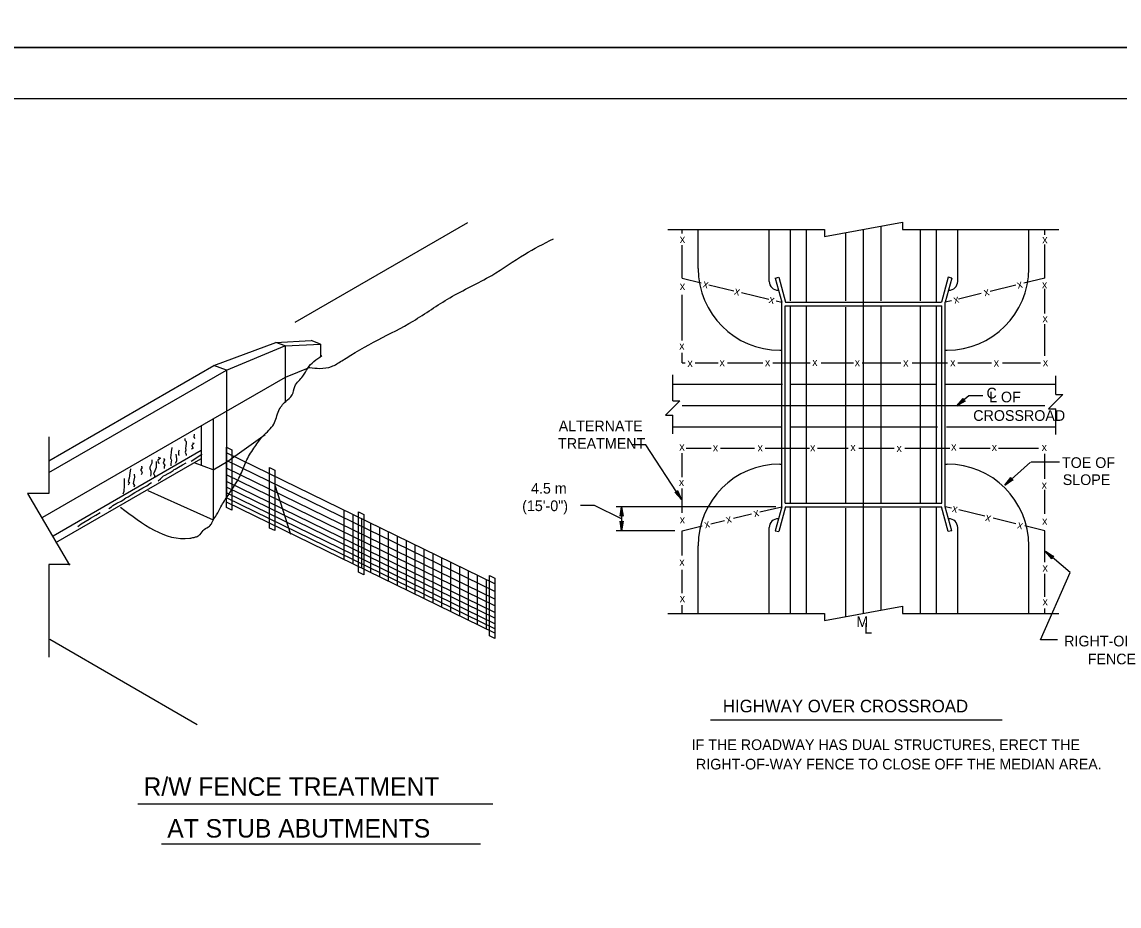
# Model space of a CAD drawing. Extents: x 13 to 918, y -903 to 879.
# Drawn here: x 370 to 691.5, y -560.6 to -301.6 of the extents above; entities that cross this region are included whole.
import ezdxf

# ---------------------------------------------------------------- set-up
doc = ezdxf.new("R2010")
doc.units = 0
for name, color, linetype in [('1', 7, 'Continuous'), ('3', 7, 'Continuous'), ('PLT-BNDY', 7, 'Continuous')]:
    doc.layers.add(name, color=color, linetype=linetype)

msp = doc.modelspace()

# ---------------------------------------------------------------- linework, layer by layer
at = {"layer": '1'}
for p, q in [((444.36025, -395.4985), (454.8145, -394.9505)), ((447.1185, -396.45475), (447.1185, -413.01725)), ((447.13725, -396.486), (457.53525, -395.94025)), ((457.53525, -395.94025), (457.53525, -399.6465)), ((429.931, -403.5735), (429.931, -440.96725)), ((426.0435, -417.8485), (426.0435, -432.71525)), ((422.56225, -419.78175), (422.56225, -431.4255)), ((377.89575, -423.088), (377.89575, -439.75475)), ((429.931, -443.861), (429.931, -426.15275)), ((429.931, -426.15275), (431.4935, -426.91525)), ((431.4935, -426.91525), (431.4935, -444.6235)), ((426.0435, -432.71525), (426.0435, -447.58175)), ((442.58525, -449.8485), (442.58525, -432.14025)), ((442.58525, -432.14025), (444.14775, -432.90275)), ((444.14775, -432.90275), (444.14775, -450.611)), ((377.89575, -439.75475), (371.64575, -439.75475)), ((371.64575, -439.75475), (383.9165, -460.69225)), ((444.16025, -437.26525), (448.66225, -451.69225)), ((431.4935, -444.6235), (429.931, -443.861)), ((464.3435, -444.5735), (464.3435, -459.05475)), ((466.94975, -445.84425), (466.94975, -460.3255)), ((468.627, -462.81925), (468.627, -445.111)), ((468.627, -445.111), (470.1895, -445.8735)), ((470.1895, -445.8735), (470.1895, -463.58175)), ((444.14775, -450.611), (442.58525, -449.8485)), ((469.554, -447.11525), (469.554, -461.5965)), ((472.15825, -448.386), (472.15825, -462.86725)), ((474.7645, -449.65675), (474.7645, -464.138)), ((477.3685, -450.92775), (477.3685, -465.409)), ((479.97475, -452.1985), (479.97475, -466.67975)), ((482.579, -453.46725), (482.579, -467.9485)), ((485.18325, -454.738), (485.18325, -469.21925)), ((487.7895, -456.009), (487.7895, -470.49025)), ((490.3935, -457.27975), (490.3935, -471.761)), ((492.99975, -458.5505), (492.99975, -473.03175)), ((384.14575, -460.588), (377.89575, -460.588)), ((377.89575, -460.588), (377.89575, -487.6715)), ((470.1895, -463.58175), (468.627, -462.81925)), ((495.604, -459.8215), (495.604, -474.30275)), ((498.20825, -461.09025), (498.20825, -475.5715)), ((500.8145, -462.363), (500.8145, -476.84425)), ((503.4185, -463.63175), (503.4185, -478.113)), ((506.02475, -464.90275), (506.02475, -479.3505)), ((507.054, -481.4465), (507.054, -463.738)), ((507.054, -463.738), (508.6165, -464.5005)), ((508.6165, -464.5005), (508.6165, -482.209)), ((508.629, -466.1735), (508.629, -479.3505)), ((605.1475, -476.938), (628.064, -472.7715)), ((605.1475, -474.85475), (605.1475, -476.938)), ((628.064, -472.7715), (628.064, -474.85475)), ((508.6165, -482.209), (507.054, -481.4465))]:
    msp.add_line(p, q, dxfattribs=at)
for points in [[(837.2505, -888.06975), (837.2505, -324.06975), (51.2505, -324.06975), (51.2505, -888.06975), (837.2505, -888.06975), (837.2505, -861.71075), (637.2505, -861.71075), (637.2505, -797.03325), (837.2505, -797.03325), (837.2505, -768.06975), (637.2505, -768.06975), (637.2505, -888.06975), (716.052, -888.06975), (716.052, -861.71075), (716.052, -888.06975), (793.052, -888.06975), (793.052, -861.71075), (793.052, -874.02725), (837.2505, -874.02725)], [(605.1475, -362.35475), (605.1475, -364.438), (628.064, -360.2715), (628.064, -362.35475)], [(646.21825, -412.62975), (646.0225, -412.54225), (643.9495, -414.036), (646.21825, -412.62975), (646.3975, -412.636), (643.9495, -414.036), (645.8515, -412.336), (645.80575, -412.12975), (643.9495, -414.036), (645.837, -411.94225), (645.80575, -412.12975)], [(417.779, -423.5965), (417.702, -424.15475), (418.181, -424.538), (418.106, -425.0965), (418.029, -425.73175), (417.952, -426.5215), (418.029, -427.07775), (417.854, -427.636), (418.181, -428.2715), (418.106, -428.57975)], [(420.47075, -422.32775), (420.39575, -423.19225), (420.702, -423.5965)], [(413.91225, -426.29025), (413.75825, -427.559), (413.75825, -427.86725), (413.604, -428.4255), (413.50825, -429.36725), (413.83525, -430.00275), (413.75825, -430.388), (413.604, -431.0985), (413.681, -431.65675)], [(416.12275, -427.0005), (415.8935, -427.386), (415.8935, -428.4255), (416.04775, -428.50275)], [(419.9895, -424.86525), (420.47075, -425.01925), (419.76025, -425.65475), (419.83725, -425.809), (420.1645, -426.44425), (419.68325, -426.7505)], [(408.0645, -429.8485), (408.0645, -430.86725), (407.506, -431.984), (407.506, -432.36925), (407.73725, -433.234), (407.73725, -434.11925), (407.66025, -434.65675)], [(409.3145, -430.386), (409.3145, -432.138), (408.91025, -433.07975), (408.602, -434.0235), (408.756, -434.1965), (408.91025, -434.811)], [(409.9685, -429.059), (410.58325, -429.36725), (409.87275, -429.9255), (409.9685, -430.713), (410.19775, -430.86725), (410.12275, -430.94425)], [(409.8915, -436.061), (410.62275, -435.42775), (411.2185, -434.82975), (411.506, -434.6005), (412.006, -434.3505), (412.83525, -433.90675), (413.4685, -433.561), (414.3145, -433.0235), (414.604, -432.734), (414.8935, -432.61925), (415.931, -432.04225), (417.0665, -431.3485), (418.181, -430.75275)], [(411.47075, -429.44425), (411.777, -429.90475), (411.54775, -430.386), (411.3935, -430.86725), (411.854, -431.484), (411.69975, -431.963), (411.69975, -432.44425)], [(415.104, -428.1755), (415.25825, -429.5985), (415.354, -430.311), (414.94975, -430.9465)], [(419.606, -430.234), (422.76025, -428.1755), (422.56225, -428.29425)], [(401.81225, -432.54025), (401.65825, -433.79225), (401.427, -435.21525), (401.177, -436.25275), (401.504, -436.484), (401.09975, -437.2735)], [(404.90825, -431.811), (405.1395, -431.811), (405.1395, -432.29225), (404.73525, -432.8485), (405.06225, -433.15675), (405.2935, -433.71525), (404.98525, -434.2735)], [(395.502, -444.1215), (396.252, -443.67975), (396.579, -443.3715), (396.6935, -443.2755), (397.8685, -442.54425), (399.13725, -441.9485), (399.5415, -441.659), (400.427, -441.0255), (401.15825, -440.67775), (401.98525, -440.14025), (403.12075, -439.4485), (404.004, -438.909), (404.254, -438.71725), (405.4665, -438.11925), (406.602, -437.4465), (407.48725, -436.79225), (407.98725, -436.563)], [(400.004, -435.39025), (399.927, -437.3505), (399.84975, -439.17975), (399.59975, -439.89025)], [(402.927, -434.04225), (403.004, -434.90675), (402.84975, -435.8505), (402.59975, -436.79225), (403.004, -437.42775), (402.84975, -437.909)], [(660.24525, -435.738), (660.04525, -435.661), (658.0495, -437.25475), (660.24525, -435.738), (660.4245, -435.734), (658.0495, -437.25475), (659.86625, -435.463), (659.80775, -435.259), (658.0495, -437.25475), (659.83075, -435.06925), (659.80775, -435.259)], [(562.0765, -439.05275), (561.97025, -439.24025), (563.2515, -441.4485), (562.0765, -439.05275), (562.0975, -438.8755), (563.2515, -441.4485), (561.7475, -439.388), (561.539, -439.413), (563.2515, -441.4485), (561.35375, -439.363), (561.539, -439.413)], [(386.42275, -449.43175), (387.3645, -448.64225), (389.731, -447.21925), (390.13525, -446.988), (391.71225, -446.10275), (392.98325, -445.31525)], [(671.78075, -458.69225), (671.82875, -458.48175), (669.9765, -456.7235), (671.78075, -458.69225), (671.80775, -458.86925), (669.9765, -456.7235), (671.9995, -458.27775), (672.19325, -458.19225), (669.9765, -456.7235), (672.385, -458.19025), (672.19325, -458.19225)]]:
    msp.add_lwpolyline(points, dxfattribs=at)
for points in [[(454.26025, -402.7715), (457.34975, -403.09025), (460.7165, -402.53175), (463.7165, -400.87775), (474.41225, -394.70275), (484.60825, -389.24025), (495.381, -382.39225), (507.67275, -375.83175), (517.31025, -369.6755), (525.731, -365.07775)], [(398.90825, -443.736), (419.206, -452.8215), (420.43525, -452.60475), (421.377, -452.2985), (422.252, -451.71925), (423.43525, -450.24025), (425.01225, -449.27775), (425.64775, -448.336), (426.0435, -447.58175), (427.07075, -445.96925), (428.3415, -443.60275), (430.39975, -440.2755), (431.977, -437.909), (434.3435, -433.638), (435.92075, -429.8485), (438.28725, -426.04025), (440.67275, -422.886), (443.827, -419.40275), (445.24975, -415.459), (447.30825, -412.76725), (449.1935, -410.863), (450.002, -408.34225), (452.3685, -405.34025), (453.7915, -402.9755), (455.52275, -401.0715), (457.8895, -399.34025)]]:
    msp.add_spline(points, degree=3, dxfattribs=at)
at = {"layer": '3'}
for p, q in [((450.0685, -389.54225), (500.656, -360.338)), ((559.314, -362.35475), (605.1475, -362.35475)), ((563.48075, -363.57975), (563.48075, -362.35475)), ((568.16825, -373.813), (568.16825, -362.35475)), ((589.0015, -377.584), (589.0015, -362.35475)), ((595.2515, -383.29025), (595.2515, -362.35475)), ((599.939, -383.4505), (599.939, -362.35475)), ((616.60575, -474.85475), (616.60575, -362.35475)), ((621.814, -383.29025), (621.814, -361.61725)), ((628.064, -362.35475), (673.8975, -362.35475)), ((633.2725, -383.29025), (633.2725, -362.35475)), ((637.96, -383.71925), (637.96, -362.35475)), ((644.21, -377.584), (644.21, -362.35475)), ((665.04325, -373.813), (665.04325, -362.35475)), ((669.73075, -363.963), (669.73075, -362.35475)), ((611.3975, -383.29025), (611.3975, -363.309)), ((563.48075, -376.67775), (563.48075, -366.94425)), ((669.73075, -376.67775), (669.73075, -366.811)), ((563.48075, -376.67775), (569.04525, -378.01925)), ((571.312, -378.56525), (578.61825, -380.3255)), ((590.76, -376.66725), (591.76625, -376.3965)), ((590.76, -376.66725), (592.6475, -383.709)), ((591.76625, -376.3965), (593.7265, -383.709)), ((641.44525, -376.3965), (639.485, -383.709)), ((642.4515, -376.66725), (640.564, -383.709)), ((642.4515, -376.66725), (641.44525, -376.3965)), ((661.23075, -378.7255), (653.71825, -380.538)), ((669.73075, -376.67775), (663.61, -378.15275)), ((563.48075, -394.8965), (563.48075, -381.50675)), ((580.8265, -380.859), (588.90775, -382.80675)), ((591.60575, -380.188), (591.70375, -380.188)), ((641.50775, -380.188), (641.60575, -380.188)), ((651.089, -381.1715), (644.489, -382.763)), ((669.73075, -386.9715), (669.73075, -379.81525)), ((591.04525, -383.3235), (592.6475, -383.709)), ((592.6475, -443.60475), (592.6475, -383.709)), ((593.689, -384.7505), (639.5225, -384.7505)), ((593.689, -442.563), (593.689, -384.7505)), ((593.7265, -383.709), (639.485, -383.709)), ((595.2515, -442.636), (595.2515, -384.69225)), ((599.939, -442.39225), (599.939, -384.89225)), ((611.3975, -442.39225), (611.3975, -385.17775)), ((621.814, -442.636), (621.814, -384.934)), ((633.2725, -442.636), (633.2725, -384.69225)), ((637.96, -442.636), (637.96, -384.69225)), ((639.5225, -442.563), (639.5225, -384.7505)), ((642.38075, -383.2715), (640.564, -383.709)), ((640.564, -443.60475), (640.564, -383.709)), ((669.73075, -399.436), (669.73075, -390.086)), ((457.53525, -395.94025), (454.8145, -394.9505)), ((426.24775, -402.234), (444.42275, -395.4755)), ((429.931, -403.5735), (447.0645, -396.47775)), ((447.1185, -396.45475), (444.42275, -395.4755)), ((563.48075, -401.41725), (563.48075, -398.53175)), ((592.1265, -397.7715), (592.6475, -397.7715)), ((640.564, -397.7715), (641.085, -397.7715)), ((563.48075, -401.41725), (564.40575, -401.41725)), ((567.2725, -401.41725), (574.0245, -401.41725)), ((576.75575, -401.41725), (587.162, -401.41725)), ((590.01, -401.41725), (600.937, -401.41725)), ((604.187, -401.41725), (613.67025, -401.41725)), ((616.26825, -401.41725), (627.57875, -401.41725)), ((630.83075, -401.41725), (641.21825, -401.41725)), ((644.21825, -401.41725), (654.087, -401.41725)), ((657.339, -401.41725), (668.514, -401.41725)), ((377.89575, -430.1465), (426.24775, -402.234)), ((377.9435, -433.586), (429.931, -403.5735)), ((429.931, -403.5735), (426.24775, -402.234)), ((447.23325, -405.61525), (454.46025, -402.69025)), ((560.7015, -412.5715), (560.7015, -404.9755)), ((426.0435, -417.8485), (447.23325, -405.61525)), ((560.7015, -407.66725), (592.85375, -407.66725)), ((595.43075, -407.66725), (637.82875, -407.66725)), ((640.4265, -407.66725), (672.9475, -407.66725)), ((672.9475, -410.7215), (672.9475, -405.284)), ((647.50775, -411.161), (643.9495, -414.036)), ((651.61, -411.161), (647.50775, -411.161)), ((563.48075, -413.91725), (669.73075, -413.91725)), ((376.177, -446.636), (426.0435, -417.8485)), ((560.7015, -422.26925), (560.7015, -416.738)), ((672.9475, -422.4235), (672.9475, -414.888)), ((560.7015, -420.16725), (592.61, -420.16725)), ((595.20775, -420.16725), (638.29525, -420.16725)), ((640.89325, -420.16725), (672.9475, -420.16725)), ((430.37275, -430.26525), (441.27275, -422.4985)), ((379.2145, -452.0985), (422.5415, -427.084)), ((552.787, -425.511), (548.7325, -425.511)), ((563.2515, -441.4485), (552.787, -425.511)), ((564.6745, -426.41725), (571.94525, -426.41725)), ((574.67875, -426.41725), (584.68075, -426.41725)), ((587.7975, -426.41725), (600.8015, -426.41725)), ((603.1475, -426.41725), (612.112, -426.41725)), ((615.22875, -426.41725), (625.61625, -426.41725)), ((628.7515, -426.41725), (641.8725, -426.41725)), ((644.739, -426.41725), (653.7015, -426.41725)), ((656.164, -426.41725), (667.86, -426.41725)), ((379.9685, -454.06925), (422.42475, -429.559)), ((426.0435, -432.76525), (430.37275, -430.26525)), ((508.629, -466.1735), (429.931, -427.79025)), ((508.629, -468.488), (429.931, -430.10475)), ((563.48075, -434.92775), (563.48075, -427.90675)), ((665.5725, -430.53175), (658.0495, -437.25475)), ((674.07875, -430.53175), (665.78275, -430.53175)), ((669.73075, -435.4465), (669.73075, -428.15675)), ((426.0435, -432.76525), (420.73525, -430.834)), ((508.629, -470.661), (429.931, -432.27775)), ((592.1265, -431.10475), (592.6475, -431.10475)), ((640.564, -431.10475), (641.085, -431.10475)), ((508.629, -472.686), (429.931, -434.30275)), ((508.629, -474.56925), (429.931, -436.186)), ((426.181, -447.5965), (406.98725, -439.00475)), ((508.629, -476.309), (429.931, -437.9255)), ((508.629, -477.9005), (429.931, -439.51725)), ((563.48075, -445.4505), (563.48075, -438.29425)), ((669.73075, -445.71925), (669.73075, -438.6985)), ((508.629, -479.3505), (429.931, -440.96725)), ((508.629, -480.65475), (429.931, -442.2715)), ((537.788, -443.27475), (533.7335, -443.27475)), ((545.7475, -447.11925), (537.788, -443.27475)), ((590.96625, -443.60475), (544.1015, -443.60475)), ((545.7475, -443.60475), (545.7475, -450.636)), ((586.25775, -445.14425), (592.6475, -443.60475)), ((592.6475, -443.60475), (590.76, -450.6465)), ((593.7265, -443.60475), (591.76625, -450.91725)), ((593.689, -442.563), (639.5225, -442.563)), ((593.7265, -443.60475), (639.485, -443.60475)), ((641.44525, -450.913), (639.485, -443.60475)), ((642.4515, -450.64225), (640.564, -443.60475)), ((642.387, -444.04425), (640.564, -443.60475)), ((578.5495, -447.00475), (583.78275, -445.74225)), ((595.2515, -474.85475), (595.2515, -443.75675)), ((599.939, -474.85475), (599.939, -443.813)), ((611.3975, -475.72975), (611.3975, -444.05675)), ((621.814, -474.036), (621.814, -444.05675)), ((633.2725, -474.85475), (633.2725, -444.05675)), ((637.96, -474.85475), (637.96, -443.89225)), ((652.164, -446.4005), (644.4995, -444.55275)), ((563.48075, -450.636), (569.38075, -449.213)), ((571.85575, -448.61725), (575.8495, -447.65475)), ((589.0015, -474.85475), (589.0015, -449.72975)), ((591.60575, -447.1255), (591.70375, -447.1255)), ((641.50775, -447.1235), (641.60575, -447.1235)), ((644.21, -474.85475), (644.21, -449.72775)), ((661.239, -448.588), (654.61, -446.99025)), ((669.73075, -450.636), (663.84125, -449.21525)), ((561.29325, -450.636), (544.1015, -450.636)), ((563.48075, -457.934), (563.48075, -450.636)), ((590.76, -450.6465), (591.76625, -450.91725)), ((642.4515, -450.64225), (641.44525, -450.913)), ((669.73075, -459.87775), (669.73075, -450.636)), ((568.16825, -474.85475), (568.16825, -455.063)), ((665.04325, -474.85475), (665.04325, -455.063)), ((677.20775, -462.86725), (669.9765, -456.7235)), ((563.48075, -468.97775), (563.48075, -462.09025)), ((668.514, -482.64425), (677.20775, -462.86725)), ((669.73075, -470.01525), (669.73075, -463.263)), ((563.48075, -474.85475), (563.48075, -472.47775)), ((559.314, -474.85475), (605.1475, -474.85475)), ((628.064, -474.85475), (673.8975, -474.85475)), ((669.73075, -474.85475), (669.73075, -473.4005)), ((421.3645, -507.4715), (378.1935, -482.5465)), ((673.44325, -482.64425), (668.514, -482.64425)), ((571.814, -506.0465), (657.23075, -506.0465)), ((508.0415, -530.7755), (403.9915, -530.7755)), ((504.38325, -542.488), (410.9415, -542.488))]:
    msp.add_line(p, q, dxfattribs=at)
for points in [[(672.9475, -410.7215), (675.03075, -410.7215), (670.864, -414.888), (672.9475, -414.888)], [(560.7015, -412.5715), (562.785, -412.5715), (558.61825, -416.738), (560.7015, -416.738)], [(545.414, -446.25275), (545.60575, -446.15475), (545.7475, -443.60475), (545.414, -446.25275), (545.2995, -446.39025), (545.7475, -443.60475), (545.8725, -446.15275), (546.064, -446.2465), (545.7475, -443.60475), (546.189, -446.39025), (546.064, -446.2465)], [(546.08075, -447.988), (545.889, -448.086), (545.7475, -450.636), (546.08075, -447.988), (546.19525, -447.8505), (545.7475, -450.636), (545.6225, -448.088), (545.43075, -447.99425), (545.7475, -450.636), (545.30575, -447.8505), (545.43075, -447.99425)]]:
    msp.add_lwpolyline(points, dxfattribs=at)
for centre, radius, start, end in [((592.12581, -373.81387), 23.9575, 180, 270), ((641.08581, -373.81387), 23.9575, 270, 0), ((591.60664, -377.58304), 2.605, 180, 270), ((641.60497, -377.58304), 2.605, 270, 0), ((592.12581, -455.06221), 23.9575, 90, 180), ((641.08581, -455.06221), 23.9575, 0, 90), ((591.60664, -449.73054), 2.605, 90, 180), ((641.60497, -449.72846), 2.605, 0, 90)]:
    msp.add_arc(centre, radius, start, end, dxfattribs=at)
at = {"layer": 'PLT-BNDY'}
for points in [[(13.2505, 284.93025), (854.2505, 284.93025), (854.2505, -309.06975), (13.2505, -309.06975)], [(13.2505, -309.06975), (854.2505, -309.06975), (854.2505, -903.06975), (13.2505, -903.06975)]]:
    msp.add_lwpolyline(points, close=True, dxfattribs=at)

# ---------------------------------------------------------------- texts
at = {"layer": '1'}
for s, height, p in [('ALTERNATE', 3.124999, (527.3085, -421.51425)), ('TREATMENT', 3.124999, (527.11875, -426.62575)), ('TOE OF', 3.124999, (674.76825, -432.25275)), ('SLOPE', 3.124999, (674.9975, -437.25475)), ('M', 3.125, (614.51825, -478.90275)), ('L', 3.125, (616.80575, -480.788)), ('RIGHT-OF-WAY', 3.1249995, (675.42025, -484.54025)), ('FENCE', 3.124999, (682.30775, -489.79025))]:
    msp.add_text(s, height=height, dxfattribs=at).set_placement(p)
at = {"layer": '3'}
for s, height, p in [('x', 2.34584, (562.78275, -366.32975)), ('x', 2.34584, (668.989, -366.4255)), ('x', 2.34584, (562.78275, -380.084)), ('x', 2.34584, (668.89325, -379.64225)), ('x', 2.34584, (669.06625, -389.586)), ('x', 2.34584, (562.61, -397.59025)), ('x', 2.34584, (565.014, -402.6485)), ('x', 2.34584, (574.42025, -402.4755)), ('x', 2.34584, (587.73275, -402.4755)), ('x', 2.34584, (601.58275, -402.37975)), ('x', 2.34584, (614.02875, -402.4755)), ('x', 2.34584, (628.2265, -402.55275)), ('x', 2.34584, (641.9995, -402.4755)), ('x', 2.34584, (654.7725, -402.55275)), ('x', 2.34584, (669.162, -402.4755)), ('C', 3.125, (652.66, -411.88175)), ('L OF', 3.124999, (653.40375, -413.0215)), ('CROSSROAD', 3.124999, (648.7745, -418.45675)), ('x', 2.34584, (562.637, -427.14025)), ('x', 2.34584, (572.45775, -427.4255)), ('x', 2.34584, (585.55775, -427.4255)), ('x', 2.34584, (600.9495, -427.4255)), ('x', 2.34584, (612.75775, -427.29025)), ('x', 2.34584, (626.28275, -427.57975)), ('x', 2.34584, (642.29325, -427.14025)), ('x', 2.34584, (654.1765, -427.29025)), ('x', 2.34584, (668.80775, -427.29025)), ('4.5 m', 3.124999, (519.18725, -439.77625)), ('x', 2.34584, (562.50575, -437.56725)), ('x', 2.34584, (668.80775, -438.35275)), ('(15\'-0")', 3.124999, (516.6005, -444.90125)), ('x', 2.34584, (562.76625, -448.51725)), ('x', 2.34584, (668.939, -448.909)), ('x', 2.34584, (562.637, -460.90475)), ('x', 2.34584, (669.06825, -462.6235)), ('x', 2.34584, (562.76625, -471.59425)), ('x', 2.34584, (669.06825, -472.52775)), ('HIGHWAY OVER CROSSROAD', 3.6770865, (575.41, -503.85275)), ('IF THE ROADWAY HAS DUAL STRUCTURES, ERECT THE', 3.1249995, (566.264, -514.90675)), ('RIGHT-OF-WAY FENCE TO CLOSE OFF THE MEDIAN AREA.', 3.1249995, (567.52875, -520.60475)), ('R/W FENCE TREATMENT', 5.4020865, (405.64775, -528.31525)), ('AT STUB ABUTMENTS', 5.4020865, (412.602, -540.5505))]:
    msp.add_text(s, height=height, dxfattribs=at).set_placement(p)
for rotation, p in [(346.4462361, (569.37025, -379.313)), (13.5537639, (661.86, -379.74425)), (346.4462361, (578.60375, -381.39025)), (346.4462361, (588.74125, -383.85275)), (13.5537639, (643.2765, -384.16925)), (13.5537639, (652.1245, -381.95675)), (346.4462361, (642.412, -445.084)), (13.5537639, (576.6015, -448.51525)), (13.5537639, (584.662, -446.688)), (346.4462361, (652.16625, -447.68175)), (13.5537639, (570.235, -449.94025)), (346.4462361, (661.53275, -449.89225))]:
    msp.add_text('x', height=2.34584, rotation=rotation, dxfattribs=at).set_placement(p)

doc.saveas('drawing.dxf')
